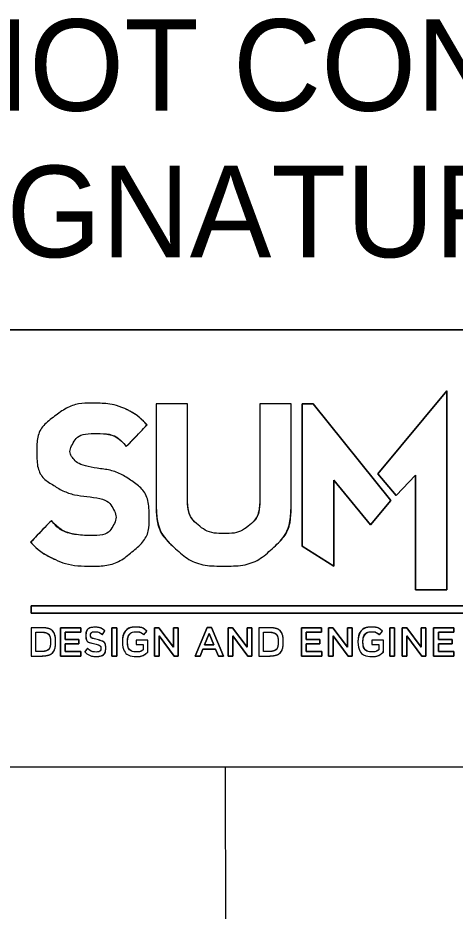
# Model space of a CAD drawing. Extents: x 1977705 to 1981198, y 827296 to 829291.
# Drawn here: x 1980880.5 to 1980905, y 828475.4 to 828525.5 of the extents above; entities that cross this region are included whole.
import ezdxf

# ---------------------------------------------------------------- set-up
doc = ezdxf.new("R2010")
doc.units = 0
for name, color, linetype in [('Level 12', 7, 'Continuous'), ('Level 13', 7, 'Continuous'), ('Level 34', 7, 'Continuous')]:
    doc.layers.add(name, color=color, linetype=linetype)

msp = doc.modelspace()

# ---------------------------------------------------------------- linework, layer by layer
at = {"layer": 'Level 12'}
for p, q in [((1980886.571, 828501.488), (1980887.74, 828502.707)), ((1980882.362, 828497.344), (1980881.193, 828496.125)), ((1980885.225, 828490.941), (1980885.369, 828491.152)), ((1980887.555, 828490.93), (1980887.725, 828491.141)), ((1980900.784, 828490.93), (1980900.954, 828491.141)), ((1980884.296, 828490.891), (1980884.296, 828490.887)), ((1980884.563, 828490.912), (1980884.563, 828490.916)), ((1980882.317, 828490.535), (1980882.317, 828490.53)), ((1980882.598, 828490.535), (1980882.598, 828490.539)), ((1980884.395, 828490.172), (1980884.235, 828489.972)), ((1980885.147, 828490.169), (1980885.147, 828490.165)), ((1980885.415, 828490.192), (1980885.415, 828490.197)), ((1980886.353, 828490.535), (1980886.353, 828490.53)), ((1980886.634, 828490.535), (1980886.634, 828490.539)), ((1980895.104, 828490.535), (1980895.104, 828490.53)), ((1980895.384, 828490.535), (1980895.384, 828490.539)), ((1980899.582, 828490.535), (1980899.582, 828490.53)), ((1980899.863, 828490.535), (1980899.863, 828490.539))]:
    msp.add_line(p, q, dxfattribs=at)
msp.add_lwpolyline([(1980814.644, 828508.05), (1981001.67, 828508.05), (1981001.67, 828483.504), (1980814.644, 828483.504)], close=True, dxfattribs=at)
for points in [[(1980904.563, 828504.615), (1980904.563, 828493.462), (1980902.807, 828493.462), (1980902.807, 828499.895), (1980901.718, 828498.743), (1980900.695, 828499.965), (1980904.563, 828504.615)], [(1980900.695, 828499.965), (1980901.718, 828498.743), (1980902.807, 828499.895), (1980902.807, 828493.462), (1980904.563, 828493.462), (1980904.563, 828504.615), (1980900.695, 828499.965)], [(1980890.012, 828498.624), (1980890.012, 828503.889), (1980888.255, 828503.889), (1980888.255, 828498.136)], [(1980895.824, 828498.136), (1980895.824, 828503.889), (1980894.067, 828503.889), (1980894.067, 828498.624)], [(1980897.074, 828503.889), (1980901.433, 828498.464), (1980900.282, 828497.098), (1980898.225, 828499.612), (1980898.225, 828494.782), (1980896.454, 828495.904), (1980896.454, 828503.889), (1980897.074, 828503.889)], [(1980896.454, 828503.889), (1980896.454, 828495.904), (1980898.225, 828494.782), (1980898.225, 828499.612), (1980900.282, 828497.098), (1980901.433, 828498.464), (1980897.074, 828503.889), (1980896.454, 828503.889)], [(1980923.801, 828492.14), (1980881.227, 828492.14), (1980881.227, 828492.563), (1980923.801, 828492.563), (1980923.801, 828492.14)], [(1980923.801, 828492.563), (1980881.227, 828492.563), (1980881.227, 828492.14), (1980923.801, 828492.14), (1980923.801, 828492.563)], [(1980881.788, 828491.33), (1980881.219, 828491.33), (1980881.219, 828489.74), (1980881.788, 828489.74)], [(1980881.788, 828489.994), (1980881.487, 828489.994), (1980881.487, 828491.075), (1980881.788, 828491.075)], [(1980882.878, 828491.33), (1980884.008, 828491.33), (1980884.008, 828491.08), (1980883.146, 828491.08), (1980883.146, 828490.667), (1980883.91, 828490.667), (1980883.91, 828490.417), (1980883.146, 828490.417), (1980883.146, 828489.99), (1980884.019, 828489.99), (1980884.019, 828489.74), (1980882.878, 828489.74), (1980882.878, 828491.33)], [(1980882.878, 828489.74), (1980884.019, 828489.74), (1980884.019, 828489.99), (1980883.146, 828489.99), (1980883.146, 828490.417), (1980883.91, 828490.417), (1980883.91, 828490.667), (1980883.146, 828490.667), (1980883.146, 828491.08), (1980884.008, 828491.08), (1980884.008, 828491.33), (1980882.878, 828491.33), (1980882.878, 828489.74)], [(1980885.767, 828491.33), (1980886.035, 828491.33), (1980886.035, 828489.74), (1980885.767, 828489.74), (1980885.767, 828491.33)], [(1980885.767, 828489.74), (1980886.035, 828489.74), (1980886.035, 828491.33), (1980885.767, 828491.33), (1980885.767, 828489.74)], [(1980888.149, 828491.33), (1980888.397, 828491.33), (1980889.214, 828490.231), (1980889.214, 828491.33), (1980889.478, 828491.33), (1980889.478, 828489.74), (1980889.253, 828489.74), (1980888.413, 828490.871), (1980888.413, 828489.74), (1980888.149, 828489.74), (1980888.149, 828491.33)], [(1980888.149, 828489.74), (1980888.413, 828489.74), (1980888.413, 828490.871), (1980889.253, 828489.74), (1980889.478, 828489.74), (1980889.478, 828491.33), (1980889.214, 828491.33), (1980889.214, 828490.231), (1980888.397, 828491.33), (1980888.149, 828491.33), (1980888.149, 828489.74)], [(1980891.106, 828491.341), (1980891.354, 828491.341), (1980892.025, 828489.74), (1980891.742, 828489.74), (1980891.587, 828490.124), (1980890.866, 828490.124), (1980890.71, 828489.74), (1980890.435, 828489.74), (1980891.106, 828491.341)], [(1980890.435, 828489.74), (1980890.71, 828489.74), (1980890.866, 828490.124), (1980891.587, 828490.124), (1980891.742, 828489.74), (1980892.025, 828489.74), (1980891.354, 828491.341), (1980891.106, 828491.341), (1980890.435, 828489.74)], [(1980892.286, 828491.33), (1980892.534, 828491.33), (1980893.351, 828490.231), (1980893.351, 828491.33), (1980893.614, 828491.33), (1980893.614, 828489.74), (1980893.39, 828489.74), (1980892.549, 828490.871), (1980892.549, 828489.74), (1980892.286, 828489.74), (1980892.286, 828491.33)], [(1980892.286, 828489.74), (1980892.549, 828489.74), (1980892.549, 828490.871), (1980893.39, 828489.74), (1980893.614, 828489.74), (1980893.614, 828491.33), (1980893.351, 828491.33), (1980893.351, 828490.231), (1980892.534, 828491.33), (1980892.286, 828491.33), (1980892.286, 828489.74)], [(1980894.574, 828491.33), (1980894.006, 828491.33), (1980894.006, 828489.74), (1980894.574, 828489.74)], [(1980894.574, 828489.994), (1980894.274, 828489.994), (1980894.274, 828491.075), (1980894.574, 828491.075)], [(1980896.405, 828491.33), (1980897.536, 828491.33), (1980897.536, 828491.08), (1980896.673, 828491.08), (1980896.673, 828490.667), (1980897.438, 828490.667), (1980897.438, 828490.417), (1980896.673, 828490.417), (1980896.673, 828489.99), (1980897.546, 828489.99), (1980897.546, 828489.74), (1980896.405, 828489.74), (1980896.405, 828491.33)], [(1980896.405, 828489.74), (1980897.546, 828489.74), (1980897.546, 828489.99), (1980896.673, 828489.99), (1980896.673, 828490.417), (1980897.438, 828490.417), (1980897.438, 828490.667), (1980896.673, 828490.667), (1980896.673, 828491.08), (1980897.536, 828491.08), (1980897.536, 828491.33), (1980896.405, 828491.33), (1980896.405, 828489.74)], [(1980897.929, 828491.33), (1980898.178, 828491.33), (1980898.994, 828490.231), (1980898.994, 828491.33), (1980899.258, 828491.33), (1980899.258, 828489.74), (1980899.034, 828489.74), (1980898.193, 828490.871), (1980898.193, 828489.74), (1980897.929, 828489.74), (1980897.929, 828491.33)], [(1980897.929, 828489.74), (1980898.193, 828489.74), (1980898.193, 828490.871), (1980899.034, 828489.74), (1980899.258, 828489.74), (1980899.258, 828491.33), (1980898.994, 828491.33), (1980898.994, 828490.231), (1980898.178, 828491.33), (1980897.929, 828491.33), (1980897.929, 828489.74)], [(1980901.372, 828491.33), (1980901.64, 828491.33), (1980901.64, 828489.74), (1980901.372, 828489.74), (1980901.372, 828491.33)], [(1980901.372, 828489.74), (1980901.64, 828489.74), (1980901.64, 828491.33), (1980901.372, 828491.33), (1980901.372, 828489.74)], [(1980902.068, 828491.33), (1980902.317, 828491.33), (1980903.133, 828490.231), (1980903.133, 828491.33), (1980903.397, 828491.33), (1980903.397, 828489.74), (1980903.172, 828489.74), (1980902.332, 828490.871), (1980902.332, 828489.74), (1980902.068, 828489.74), (1980902.068, 828491.33)], [(1980902.068, 828489.74), (1980902.332, 828489.74), (1980902.332, 828490.871), (1980903.172, 828489.74), (1980903.397, 828489.74), (1980903.397, 828491.33), (1980903.133, 828491.33), (1980903.133, 828490.231), (1980902.317, 828491.33), (1980902.068, 828491.33), (1980902.068, 828489.74)], [(1980903.832, 828491.33), (1980904.962, 828491.33), (1980904.962, 828491.08), (1980904.1, 828491.08), (1980904.1, 828490.667), (1980904.864, 828490.667), (1980904.864, 828490.417), (1980904.1, 828490.417), (1980904.1, 828489.99), (1980904.973, 828489.99), (1980904.973, 828489.74), (1980903.832, 828489.74), (1980903.832, 828491.33)], [(1980903.832, 828489.74), (1980904.973, 828489.74), (1980904.973, 828489.99), (1980904.1, 828489.99), (1980904.1, 828490.417), (1980904.864, 828490.417), (1980904.864, 828490.667), (1980904.1, 828490.667), (1980904.1, 828491.08), (1980904.962, 828491.08), (1980904.962, 828491.33), (1980903.832, 828491.33), (1980903.832, 828489.74)], [(1980887.779, 828489.96), (1980887.779, 828490.628), (1980887.13, 828490.628), (1980887.13, 828490.385), (1980887.52, 828490.385), (1980887.52, 828490.088)], [(1980891.489, 828490.371), (1980891.226, 828491.007), (1980890.965, 828490.371), (1980891.489, 828490.371)], [(1980890.965, 828490.371), (1980891.226, 828491.007), (1980891.489, 828490.371), (1980890.965, 828490.371)], [(1980901.008, 828489.96), (1980901.008, 828490.628), (1980900.359, 828490.628), (1980900.359, 828490.385), (1980900.749, 828490.385), (1980900.749, 828490.088)]]:
    msp.add_lwpolyline(points, dxfattribs=at)
for points, degree in [([(1980886.483, 828503.621), (1980886.931, 828503.418), (1980887.35, 828503.113), (1980887.74, 828502.707), (1980887.74, 828502.707), (1980886.571, 828501.488), (1980886.571, 828501.488), (1980886.181, 828501.975), (1980885.636, 828502.219), (1980884.934, 828502.219), (1980884.233, 828502.219), (1980883.785, 828502.047), (1980883.59, 828501.701), (1980883.395, 828501.356), (1980883.395, 828501.062), (1980883.59, 828500.818), (1980883.785, 828500.574), (1980884.233, 828500.391), (1980884.934, 828500.269), (1980885.674, 828500.188), (1980886.347, 828499.934), (1980886.951, 828499.507), (1980887.555, 828499.081), (1980887.856, 828498.4), (1980887.856, 828497.466), (1980887.856, 828496.734), (1980887.534, 828496.105), (1980886.889, 828495.577), (1980886.245, 828495.048), (1980885.493, 828494.784), (1980884.636, 828494.784), (1980883.821, 828494.784), (1980883.141, 828494.906), (1980882.596, 828495.15), (1980882.05, 828495.394), (1980881.583, 828495.719), (1980881.193, 828496.125), (1980881.193, 828496.125), (1980882.362, 828497.344), (1980882.362, 828497.344), (1980882.752, 828496.856), (1980883.415, 828496.572), (1980884.35, 828496.491), (1980885.129, 828496.491), (1980885.615, 828496.663), (1980885.808, 828497.009), (1980886.001, 828497.354), (1980886.001, 828497.699), (1980885.808, 828498.045), (1980885.615, 828498.39), (1980885.129, 828498.603), (1980884.35, 828498.684), (1980883.648, 828498.766), (1980883.005, 828498.989), (1980882.421, 828499.355), (1980881.836, 828499.721), (1980881.544, 828500.35), (1980881.544, 828501.244), (1980881.544, 828502.053), (1980881.876, 828502.701), (1980882.54, 828503.191), (1980883.205, 828503.681), (1980883.888, 828503.926), (1980884.589, 828503.926), (1980885.404, 828503.926), (1980886.035, 828503.825), (1980886.483, 828503.621)], 3), ([(1980886.483, 828503.621), (1980886.035, 828503.825), (1980885.404, 828503.926), (1980884.589, 828503.926), (1980883.888, 828503.926), (1980883.205, 828503.681), (1980882.54, 828503.191), (1980881.876, 828502.701), (1980881.544, 828502.053), (1980881.544, 828501.244), (1980881.544, 828500.35), (1980881.836, 828499.721), (1980882.421, 828499.355), (1980883.005, 828498.989), (1980883.648, 828498.766), (1980884.35, 828498.684), (1980885.129, 828498.603), (1980885.615, 828498.39), (1980885.808, 828498.045), (1980886.001, 828497.699), (1980886.001, 828497.354), (1980885.808, 828497.009), (1980885.615, 828496.663), (1980885.129, 828496.491), (1980884.35, 828496.491), (1980883.415, 828496.572), (1980882.752, 828496.856), (1980882.362, 828497.344)], 3), ([(1980887.74, 828502.707), (1980887.35, 828503.113), (1980886.931, 828503.418), (1980886.483, 828503.621)], 2), ([(1980890.012, 828503.889), (1980890.012, 828503.889), (1980890.012, 828498.624), (1980890.012, 828498.624), (1980890.012, 828497.933), (1980890.211, 828497.425), (1980890.601, 828497.1), (1980890.991, 828496.775), (1980891.48, 828496.612), (1980892.065, 828496.612), (1980892.649, 828496.612), (1980893.114, 828496.775), (1980893.504, 828497.1), (1980893.894, 828497.425), (1980894.067, 828497.933), (1980894.067, 828498.624), (1980894.067, 828498.624), (1980894.067, 828503.889), (1980894.067, 828503.889), (1980894.067, 828503.889), (1980895.824, 828503.889), (1980895.824, 828503.889), (1980895.824, 828503.889), (1980895.824, 828498.136), (1980895.824, 828498.136), (1980895.824, 828497.201), (1980895.485, 828496.41), (1980894.763, 828495.759), (1980894.042, 828495.11), (1980893.147, 828494.784), (1980892.056, 828494.784), (1980890.965, 828494.784), (1980890.058, 828495.11), (1980889.337, 828495.759), (1980888.616, 828496.41), (1980888.255, 828497.201), (1980888.255, 828498.136), (1980888.255, 828498.136), (1980888.255, 828503.889), (1980888.255, 828503.889), (1980888.255, 828503.889), (1980890.012, 828503.889), (1980890.012, 828503.889)], 3), ([(1980881.193, 828496.125), (1980881.583, 828495.719), (1980882.05, 828495.394), (1980882.596, 828495.15), (1980883.141, 828494.906), (1980883.821, 828494.784), (1980884.636, 828494.784), (1980885.493, 828494.784), (1980886.245, 828495.048), (1980886.889, 828495.577), (1980887.534, 828496.105), (1980887.856, 828496.734), (1980887.856, 828497.466), (1980887.856, 828498.4), (1980887.555, 828499.081), (1980886.951, 828499.507), (1980886.347, 828499.934), (1980885.674, 828500.188), (1980884.934, 828500.269), (1980884.233, 828500.391), (1980883.785, 828500.574), (1980883.59, 828500.818), (1980883.395, 828501.062), (1980883.395, 828501.356), (1980883.59, 828501.701), (1980883.785, 828502.047), (1980884.233, 828502.219), (1980884.934, 828502.219), (1980885.636, 828502.219), (1980886.181, 828501.975), (1980886.571, 828501.488)], 3), ([(1980894.067, 828498.624), (1980894.067, 828497.933), (1980893.894, 828497.425), (1980893.504, 828497.1), (1980893.114, 828496.775), (1980892.649, 828496.612), (1980892.065, 828496.612), (1980891.48, 828496.612), (1980890.991, 828496.775), (1980890.601, 828497.1), (1980890.211, 828497.425), (1980890.012, 828497.933), (1980890.012, 828498.624)], 3), ([(1980888.255, 828498.136), (1980888.255, 828497.201), (1980888.616, 828496.41), (1980889.337, 828495.759), (1980890.058, 828495.11), (1980890.965, 828494.784), (1980892.056, 828494.784), (1980893.147, 828494.784), (1980894.042, 828495.11), (1980894.763, 828495.759), (1980895.485, 828496.41), (1980895.824, 828497.201), (1980895.824, 828498.136)], 3), ([(1980881.219, 828491.33), (1980881.219, 828491.33), (1980881.788, 828491.33), (1980881.788, 828491.33), (1980882.267, 828491.33), (1980882.598, 828490.987), (1980882.598, 828490.539), (1980882.598, 828490.539), (1980882.598, 828490.535), (1980882.598, 828490.535), (1980882.598, 828490.088), (1980882.267, 828489.74), (1980881.788, 828489.74), (1980881.788, 828489.74), (1980881.219, 828489.74), (1980881.219, 828489.74), (1980881.219, 828489.74), (1980881.219, 828491.33), (1980881.219, 828491.33)], 3), ([(1980881.487, 828491.075), (1980881.487, 828491.075), (1980881.487, 828489.994), (1980881.487, 828489.994), (1980881.487, 828489.994), (1980881.788, 828489.994), (1980881.788, 828489.994), (1980882.108, 828489.994), (1980882.317, 828490.219), (1980882.317, 828490.53), (1980882.317, 828490.53), (1980882.317, 828490.535), (1980882.317, 828490.535), (1980882.317, 828490.846), (1980882.108, 828491.075), (1980881.788, 828491.075), (1980881.788, 828491.075), (1980881.487, 828491.075), (1980881.487, 828491.075)], 3), ([(1980882.598, 828490.539), (1980882.598, 828490.987), (1980882.267, 828491.33), (1980881.788, 828491.33)], 2), ([(1980881.788, 828491.075), (1980882.108, 828491.075), (1980882.317, 828490.846), (1980882.317, 828490.535)], 2), ([(1980884.235, 828489.972), (1980884.235, 828489.972), (1980884.395, 828490.172), (1980884.395, 828490.172), (1980884.542, 828490.04), (1980884.69, 828489.965), (1980884.877, 828489.965), (1980885.042, 828489.965), (1980885.147, 828490.047), (1980885.147, 828490.165), (1980885.147, 828490.165), (1980885.147, 828490.169), (1980885.147, 828490.169), (1980885.147, 828490.283), (1980885.086, 828490.344), (1980884.803, 828490.412), (1980884.479, 828490.494), (1980884.296, 828490.594), (1980884.296, 828490.887), (1980884.296, 828490.887), (1980884.296, 828490.891), (1980884.296, 828490.891), (1980884.296, 828491.164), (1980884.513, 828491.352), (1980884.816, 828491.352), (1980885.038, 828491.352), (1980885.214, 828491.282), (1980885.369, 828491.152), (1980885.369, 828491.152), (1980885.225, 828490.941), (1980885.225, 828490.941), (1980885.088, 828491.048), (1980884.951, 828491.105), (1980884.812, 828491.105), (1980884.655, 828491.105), (1980884.563, 828491.021), (1980884.563, 828490.916), (1980884.563, 828490.916), (1980884.563, 828490.912), (1980884.563, 828490.912), (1980884.563, 828490.789), (1980884.633, 828490.735), (1980884.927, 828490.662), (1980885.249, 828490.58), (1980885.415, 828490.46), (1980885.415, 828490.197), (1980885.415, 828490.197), (1980885.415, 828490.192), (1980885.415, 828490.192), (1980885.415, 828489.895), (1980885.191, 828489.717), (1980884.87, 828489.717), (1980884.637, 828489.717), (1980884.417, 828489.802), (1980884.235, 828489.972)], 3), ([(1980885.369, 828491.152), (1980885.214, 828491.282), (1980885.038, 828491.352), (1980884.816, 828491.352), (1980884.513, 828491.352), (1980884.296, 828491.164), (1980884.296, 828490.891)], 3), ([(1980884.563, 828490.916), (1980884.563, 828491.021), (1980884.655, 828491.105), (1980884.812, 828491.105), (1980884.951, 828491.105), (1980885.088, 828491.048), (1980885.225, 828490.941)], 3), ([(1980886.353, 828490.53), (1980886.353, 828490.53), (1980886.353, 828490.535), (1980886.353, 828490.535), (1980886.353, 828490.98), (1980886.679, 828491.357), (1980887.139, 828491.357), (1980887.405, 828491.357), (1980887.568, 828491.28), (1980887.725, 828491.141), (1980887.725, 828491.141), (1980887.555, 828490.93), (1980887.555, 828490.93), (1980887.437, 828491.034), (1980887.322, 828491.1), (1980887.128, 828491.1), (1980886.847, 828491.1), (1980886.634, 828490.844), (1980886.634, 828490.539), (1980886.634, 828490.539), (1980886.634, 828490.535), (1980886.634, 828490.535), (1980886.634, 828490.208), (1980886.841, 828489.967), (1980887.152, 828489.967), (1980887.296, 828489.967), (1980887.426, 828490.015), (1980887.52, 828490.088), (1980887.52, 828490.088), (1980887.52, 828490.385), (1980887.52, 828490.385), (1980887.52, 828490.385), (1980887.13, 828490.385), (1980887.13, 828490.385), (1980887.13, 828490.385), (1980887.13, 828490.628), (1980887.13, 828490.628), (1980887.13, 828490.628), (1980887.779, 828490.628), (1980887.779, 828490.628), (1980887.779, 828490.628), (1980887.779, 828489.96), (1980887.779, 828489.96), (1980887.629, 828489.826), (1980887.413, 828489.713), (1980887.143, 828489.713), (1980886.667, 828489.713), (1980886.353, 828490.067), (1980886.353, 828490.53)], 3), ([(1980887.725, 828491.141), (1980887.568, 828491.28), (1980887.405, 828491.357), (1980887.139, 828491.357), (1980886.679, 828491.357), (1980886.353, 828490.98), (1980886.353, 828490.535)], 3), ([(1980886.634, 828490.539), (1980886.634, 828490.844), (1980886.847, 828491.1), (1980887.128, 828491.1), (1980887.322, 828491.1), (1980887.437, 828491.034), (1980887.555, 828490.93)], 3), ([(1980894.006, 828491.33), (1980894.006, 828491.33), (1980894.574, 828491.33), (1980894.574, 828491.33), (1980895.053, 828491.33), (1980895.384, 828490.987), (1980895.384, 828490.539), (1980895.384, 828490.539), (1980895.384, 828490.535), (1980895.384, 828490.535), (1980895.384, 828490.088), (1980895.053, 828489.74), (1980894.574, 828489.74), (1980894.574, 828489.74), (1980894.006, 828489.74), (1980894.006, 828489.74), (1980894.006, 828489.74), (1980894.006, 828491.33), (1980894.006, 828491.33)], 3), ([(1980894.274, 828491.075), (1980894.274, 828491.075), (1980894.274, 828489.994), (1980894.274, 828489.994), (1980894.274, 828489.994), (1980894.574, 828489.994), (1980894.574, 828489.994), (1980894.895, 828489.994), (1980895.104, 828490.219), (1980895.104, 828490.53), (1980895.104, 828490.53), (1980895.104, 828490.535), (1980895.104, 828490.535), (1980895.104, 828490.846), (1980894.895, 828491.075), (1980894.574, 828491.075), (1980894.574, 828491.075), (1980894.274, 828491.075), (1980894.274, 828491.075)], 3), ([(1980895.384, 828490.539), (1980895.384, 828490.987), (1980895.053, 828491.33), (1980894.574, 828491.33)], 2), ([(1980894.574, 828491.075), (1980894.895, 828491.075), (1980895.104, 828490.846), (1980895.104, 828490.535)], 2), ([(1980899.582, 828490.53), (1980899.582, 828490.53), (1980899.582, 828490.535), (1980899.582, 828490.535), (1980899.582, 828490.98), (1980899.909, 828491.357), (1980900.368, 828491.357), (1980900.634, 828491.357), (1980900.797, 828491.28), (1980900.954, 828491.141), (1980900.954, 828491.141), (1980900.784, 828490.93), (1980900.784, 828490.93), (1980900.667, 828491.034), (1980900.551, 828491.1), (1980900.357, 828491.1), (1980900.076, 828491.1), (1980899.863, 828490.844), (1980899.863, 828490.539), (1980899.863, 828490.539), (1980899.863, 828490.535), (1980899.863, 828490.535), (1980899.863, 828490.208), (1980900.07, 828489.967), (1980900.381, 828489.967), (1980900.525, 828489.967), (1980900.656, 828490.015), (1980900.749, 828490.088), (1980900.749, 828490.088), (1980900.749, 828490.385), (1980900.749, 828490.385), (1980900.749, 828490.385), (1980900.359, 828490.385), (1980900.359, 828490.385), (1980900.359, 828490.385), (1980900.359, 828490.628), (1980900.359, 828490.628), (1980900.359, 828490.628), (1980901.008, 828490.628), (1980901.008, 828490.628), (1980901.008, 828490.628), (1980901.008, 828489.96), (1980901.008, 828489.96), (1980900.858, 828489.826), (1980900.643, 828489.713), (1980900.373, 828489.713), (1980899.896, 828489.713), (1980899.582, 828490.067), (1980899.582, 828490.53)], 3), ([(1980900.954, 828491.141), (1980900.797, 828491.28), (1980900.634, 828491.357), (1980900.368, 828491.357), (1980899.909, 828491.357), (1980899.582, 828490.98), (1980899.582, 828490.535)], 3), ([(1980899.863, 828490.539), (1980899.863, 828490.844), (1980900.076, 828491.1), (1980900.357, 828491.1), (1980900.551, 828491.1), (1980900.667, 828491.034), (1980900.784, 828490.93)], 3), ([(1980884.296, 828490.887), (1980884.296, 828490.594), (1980884.479, 828490.494), (1980884.803, 828490.412), (1980885.086, 828490.344), (1980885.147, 828490.283), (1980885.147, 828490.169)], 3), ([(1980885.415, 828490.197), (1980885.415, 828490.46), (1980885.249, 828490.58), (1980884.927, 828490.662), (1980884.633, 828490.735), (1980884.563, 828490.789), (1980884.563, 828490.912)], 3), ([(1980881.788, 828489.74), (1980882.267, 828489.74), (1980882.598, 828490.088), (1980882.598, 828490.535)], 2), ([(1980882.317, 828490.53), (1980882.317, 828490.219), (1980882.108, 828489.994), (1980881.788, 828489.994)], 2), ([(1980884.235, 828489.972), (1980884.417, 828489.802), (1980884.637, 828489.717), (1980884.87, 828489.717), (1980885.191, 828489.717), (1980885.415, 828489.895), (1980885.415, 828490.192)], 3), ([(1980885.147, 828490.165), (1980885.147, 828490.047), (1980885.042, 828489.965), (1980884.877, 828489.965), (1980884.69, 828489.965), (1980884.542, 828490.04), (1980884.395, 828490.172)], 3), ([(1980886.353, 828490.53), (1980886.353, 828490.067), (1980886.667, 828489.713), (1980887.143, 828489.713), (1980887.413, 828489.713), (1980887.629, 828489.826), (1980887.779, 828489.96)], 3), ([(1980887.52, 828490.088), (1980887.426, 828490.015), (1980887.296, 828489.967), (1980887.152, 828489.967), (1980886.841, 828489.967), (1980886.634, 828490.208), (1980886.634, 828490.535)], 3), ([(1980894.574, 828489.74), (1980895.053, 828489.74), (1980895.384, 828490.088), (1980895.384, 828490.535)], 2), ([(1980895.104, 828490.53), (1980895.104, 828490.219), (1980894.895, 828489.994), (1980894.574, 828489.994)], 2), ([(1980899.582, 828490.53), (1980899.582, 828490.067), (1980899.896, 828489.713), (1980900.373, 828489.713), (1980900.643, 828489.713), (1980900.858, 828489.826), (1980901.008, 828489.96)], 3), ([(1980900.749, 828490.088), (1980900.656, 828490.015), (1980900.525, 828489.967), (1980900.381, 828489.967), (1980900.07, 828489.967), (1980899.863, 828490.208), (1980899.863, 828490.535)], 3)]:
    msp.add_open_spline(points, degree=degree, dxfattribs=at)
at = {"layer": 'Level 13'}
msp.add_line((1981001.67, 828508.05), (1980814.895, 828508.05), dxfattribs=at)
at = {"layer": 'Level 34'}
msp.add_line((1980892.549, 827737.433), (1980892.148, 828483.504), dxfattribs=at)

# ---------------------------------------------------------------- texts
at = {"layer": 'Level 13'}
for s, p in [('DOCUMENT NOT CONSIDERED FINAL', (1980834.569, 828520.332)), ('UNLESS ALL SIGNATURES COMPLETED', (1980829.834, 828512.116))]:
    msp.add_text(s, height=5.13537, dxfattribs=at).set_placement(p)

doc.saveas('drawing.dxf')
